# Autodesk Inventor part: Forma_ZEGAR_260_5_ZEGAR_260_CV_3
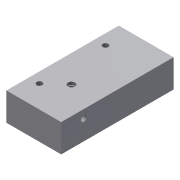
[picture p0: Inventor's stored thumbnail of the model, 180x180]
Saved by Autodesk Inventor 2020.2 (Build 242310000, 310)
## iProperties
Created: 2015-01
Part Number: Forma_ZEGAR_260_5_ZEGAR_260_CV_3
Material: Ogólny
Document SubType Name: Modeling
Designer: F.Stasiak
Density: 1 g/cm^3
Appearance: Domyślna
Catalog Web Link: www.expertbooks.pl
Manager: www.cadconsulting.pl
Company: Fabian Stasiak CAD Consulting
Author: F.Stasiak
Subject: Zbiór ćwiczeń. Autodesk Inventor 2020. Kurs Professional
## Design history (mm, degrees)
node "Forma_ZEGAR_260_4_ZEGAR_260_CV_Base"
feature "Rzeźbienie4"
feature "Gwint1" dims "d0" = 0, "d1" = 0
feature "Rzeźbienie6"
feature "Rzeźbienie8"
feature "Gwint3" dims "d4" = 0, "d5" = 0
feature "Rzeźbienie11"
feature "Bryła1::Forma_ZEGAR_260_4_ZEGAR_260_CV_Base"
tag "Bryła wyprowadzona1"
node "Bryła1"
feature "Forma_ZEGAR_260_4_ZEGAR_260_CV_Base_Bodies"
feature "Powierzchnia4"
body "Srf4"
feature "Powierzchnia6"
body "Srf6"
feature "Powierzchnia8"
body "Srf8"
feature "Powierzchnia11"
body "Srf11"
